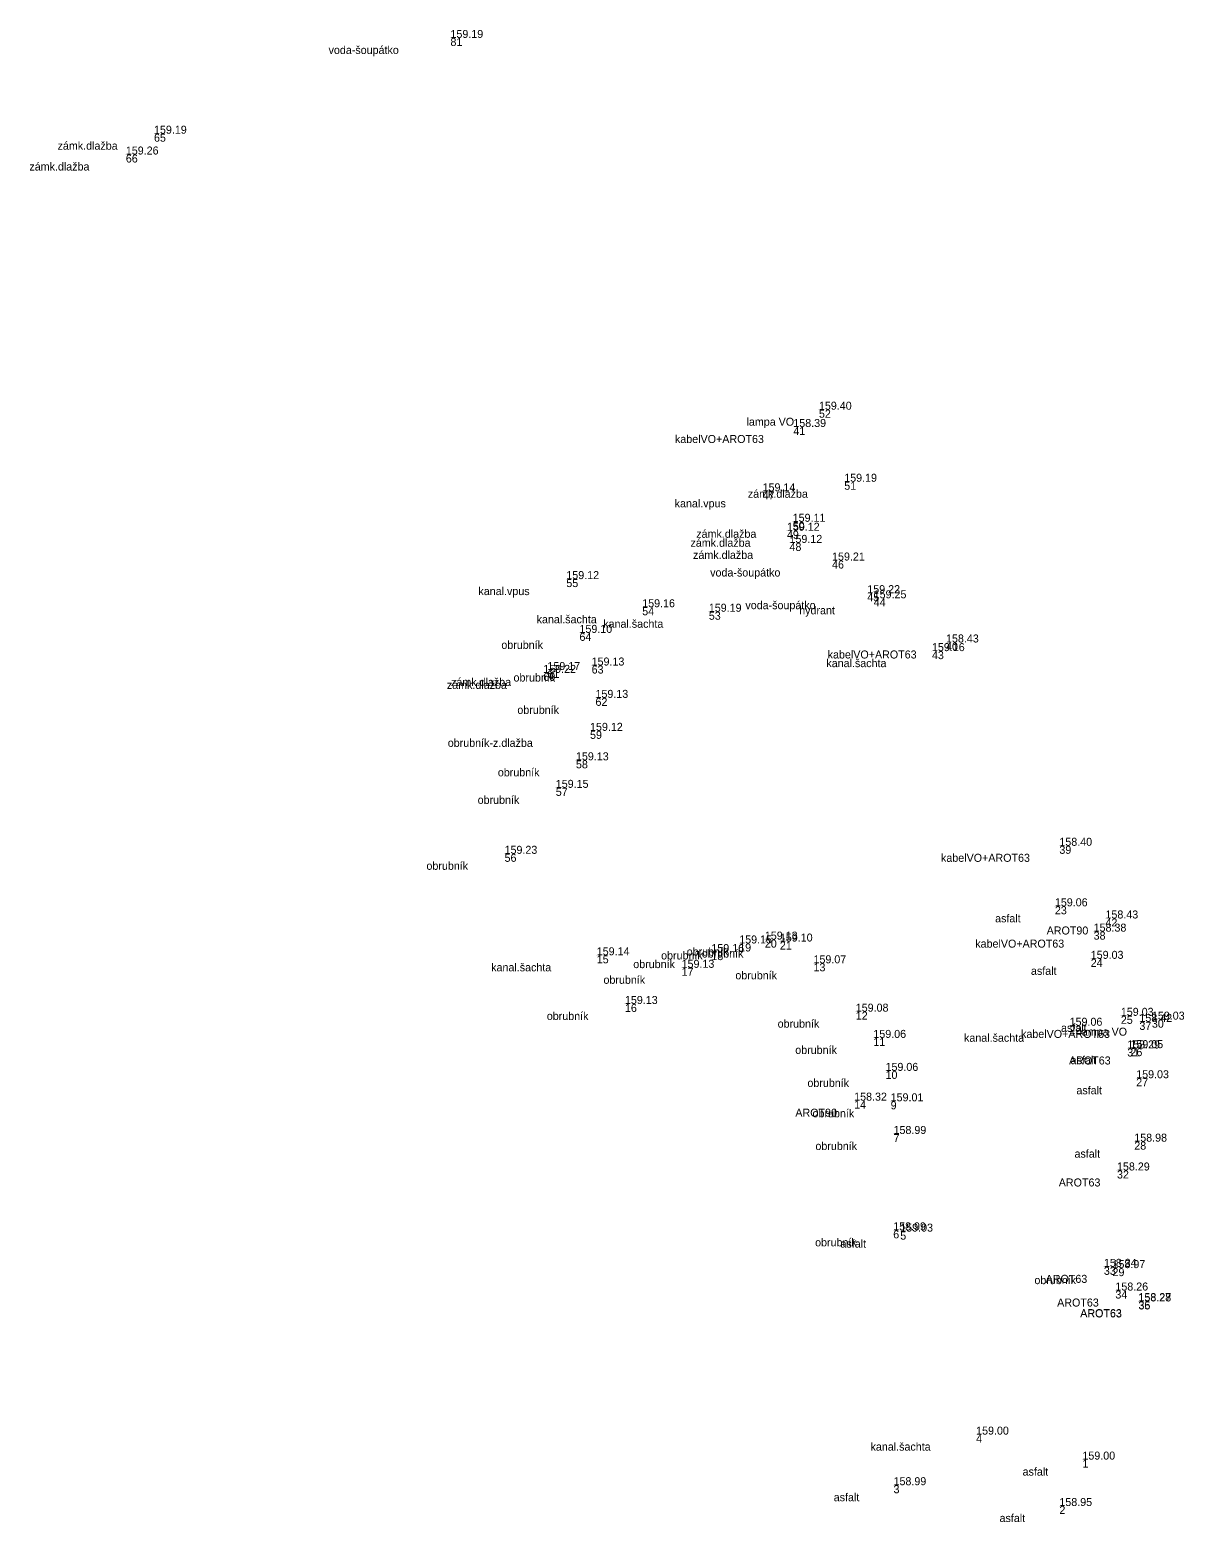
# Model space of a CAD drawing. Extents: x -583304 to -583163, y -1211038 to -1210841.
# Drawn here: x -583199 to -583162.94, y -1211037.82 to -1210991.22 of the extents above; entities that cross this region are included whole.
import ezdxf

# ---------------------------------------------------------------- set-up
doc = ezdxf.new("R2010")
doc.units = 0
for name, color, linetype in [('Vrstva 10', 7, 'Continuous'), ('Vrstva 7', 7, 'Continuous'), ('Vrstva 8', 7, 'Continuous'), ('Vrstva 9', 7, 'Continuous')]:
    doc.layers.add(name, color=color, linetype=linetype)

msp = doc.modelspace()

# ---------------------------------------------------------------- linework, layer by layer
at = {"layer": 'Vrstva 7'}
for p, q in [((-583185.86, -1210991.47), (-583185.86, -1210991.47)), ((-583195.12, -1210994.46), (-583195.12, -1210994.46)), ((-583196, -1210995.11), (-583196, -1210995.11)), ((-583174.35, -1211003.08), (-583174.35, -1211003.08)), ((-583175.15, -1211003.62), (-583175.15, -1211003.62)), ((-583176.11, -1211005.63), (-583176.11, -1211005.63)), ((-583173.56, -1211005.33), (-583173.56, -1211005.33)), ((-583175.17, -1211006.58), (-583175.17, -1211006.58)), ((-583175.35, -1211006.86), (-583175.35, -1211006.86)), ((-583175.27, -1211007.24), (-583175.27, -1211007.24)), ((-583173.94, -1211007.79), (-583173.94, -1211007.79)), ((-583182.24, -1211008.37), (-583182.24, -1211008.37)), ((-583172.84, -1211008.81), (-583172.84, -1211008.81)), ((-583179.87, -1211009.25), (-583179.87, -1211009.25)), ((-583177.79, -1211009.39), (-583177.79, -1211009.39)), ((-583172.64, -1211008.97), (-583172.64, -1211008.97)), ((-583181.83, -1211010.05), (-583181.83, -1211010.05)), ((-583170.82, -1211010.62), (-583170.82, -1211010.62)), ((-583170.38, -1211010.35), (-583170.38, -1211010.35)), ((-583182.83, -1211011.21), (-583182.83, -1211011.21)), ((-583181.45, -1211011.07), (-583181.45, -1211011.07)), ((-583182.96, -1211011.3), (-583182.96, -1211011.3)), ((-583181.33, -1211012.08), (-583181.33, -1211012.08)), ((-583181.5, -1211013.11), (-583181.5, -1211013.11)), ((-583181.94, -1211014.03), (-583181.94, -1211014.03)), ((-583182.57, -1211014.89), (-583182.57, -1211014.89)), ((-583166.84, -1211016.7), (-583166.84, -1211016.7)), ((-583184.17, -1211016.95), (-583184.17, -1211016.95)), ((-583166.98, -1211018.59), (-583166.98, -1211018.59)), ((-583165.4, -1211018.97), (-583165.4, -1211018.97)), ((-583176.04, -1211019.63), (-583176.04, -1211019.63)), ((-583165.77, -1211019.38), (-583165.77, -1211019.38)), ((-583181.29, -1211020.12), (-583181.29, -1211020.12)), ((-583177.71, -1211020.02), (-583177.71, -1211020.02)), ((-583176.84, -1211019.75), (-583176.84, -1211019.75)), ((-583175.57, -1211019.69), (-583175.57, -1211019.69)), ((-583178.64, -1211020.51), (-583178.64, -1211020.51)), ((-583174.52, -1211020.37), (-583174.52, -1211020.37)), ((-583165.86, -1211020.23), (-583165.86, -1211020.23)), ((-583180.41, -1211021.64), (-583180.41, -1211021.64)), ((-583173.2, -1211021.88), (-583173.2, -1211021.88)), ((-583166.52, -1211022.32), (-583166.52, -1211022.32)), ((-583164.92, -1211022.01), (-583164.92, -1211022.01)), ((-583164.34, -1211022.2), (-583164.34, -1211022.2)), ((-583163.95, -1211022.13), (-583163.95, -1211022.13)), ((-583172.65, -1211022.7), (-583172.65, -1211022.7)), ((-583164.72, -1211023.03), (-583164.72, -1211023.03)), ((-583164.62, -1211023.02), (-583164.62, -1211023.02)), ((-583172.27, -1211023.73), (-583172.27, -1211023.73)), ((-583164.44, -1211023.96), (-583164.44, -1211023.96)), ((-583173.25, -1211024.66), (-583173.25, -1211024.66)), ((-583172.11, -1211024.68), (-583172.11, -1211024.68)), ((-583172.02, -1211025.7), (-583172.02, -1211025.7)), ((-583164.5, -1211025.94), (-583164.5, -1211025.94)), ((-583165.04, -1211026.84), (-583165.04, -1211026.84)), ((-583172.03, -1211028.71), (-583172.03, -1211028.71)), ((-583171.81, -1211028.75), (-583171.81, -1211028.75)), ((-583165.45, -1211029.85), (-583165.45, -1211029.85)), ((-583165.18, -1211029.89), (-583165.18, -1211029.89)), ((-583165.09, -1211030.59), (-583165.09, -1211030.59)), ((-583164.37, -1211030.92), (-583164.37, -1211030.92)), ((-583164.37, -1211030.93), (-583164.37, -1211030.93)), ((-583169.44, -1211035.09), (-583169.44, -1211035.09)), ((-583166.12, -1211035.87), (-583166.12, -1211035.87)), ((-583172.02, -1211036.67), (-583172.02, -1211036.67)), ((-583166.84, -1211037.32), (-583166.84, -1211037.32))]:
    msp.add_line(p, q, dxfattribs=at)

# ---------------------------------------------------------------- texts
at = {"layer": 'Vrstva 10'}
for s, p in [('voda-šoupátko', (-583189.667, -1210991.97)), ('zámk.dlažba', (-583198.132, -1210994.96)), ('zámk.dlažba', (-583199.012, -1210995.61)), ('lampa VO', (-583176.612, -1211003.58)), ('kabelVO+AROT63', (-583178.847, -1211004.12)), ('zámk.dlažba', (-583176.572, -1211005.83)), ('kanal.vpus', (-583178.856, -1211006.13)), ('zámk.dlažba', (-583178.182, -1211007.08)), ('zámk.dlažba', (-583178.362, -1211007.36)), ('zámk.dlažba', (-583178.282, -1211007.74)), ('voda-šoupátko', (-583177.747, -1211008.29)), ('kanal.vpus', (-583184.986, -1211008.87)), ('voda-šoupátko', (-583176.647, -1211009.31)), ('hydrant', (-583174.966, -1211009.47)), ('kanal.šachta', (-583183.168, -1211009.75)), ('kanal.šachta', (-583181.088, -1211009.89)), ('obrubník', (-583184.27, -1211010.55)), ('kabelVO+AROT63', (-583174.077, -1211010.85)), ('kanal.šachta', (-583174.118, -1211011.12)), ('zámk.dlažba', (-583185.972, -1211011.8)), ('zámk.dlažba', (-583185.842, -1211011.71)), ('obrubník', (-583183.89, -1211011.57)), ('obrubník', (-583183.77, -1211012.58)), ('obrubník-z.dlažba', (-583185.944, -1211013.61)), ('obrubník', (-583184.38, -1211014.53)), ('obrubník', (-583185.01, -1211015.39)), ('obrubník', (-583186.61, -1211017.45)), ('kabelVO+AROT63', (-583170.537, -1211017.2)), ('asfalt', (-583168.848, -1211019.09)), ('kabelVO+AROT63', (-583169.467, -1211019.88)), ('AROT90', (-583167.237, -1211019.47)), ('obrubník', (-583179.28, -1211020.25)), ('obrubník', (-583178.48, -1211020.13)), ('obrubník', (-583178.01, -1211020.19)), ('kanal.šachta', (-583184.588, -1211020.62)), ('obrubník', (-583180.15, -1211020.52)), ('asfalt', (-583167.728, -1211020.73)), ('obrubník', (-583181.08, -1211021.01)), ('obrubník', (-583176.96, -1211020.87)), ('obrubník', (-583182.85, -1211022.14)), ('obrubník', (-583175.64, -1211022.38)), ('kabelVO+AROT63', (-583168.037, -1211022.7)), ('asfalt', (-583166.788, -1211022.51)), ('lampa VO', (-583166.212, -1211022.63)), ('kanal.šachta', (-583169.818, -1211022.82)), ('obrubník', (-583175.09, -1211023.2)), ('AROT63', (-583166.539, -1211023.53)), ('asfalt', (-583166.488, -1211023.52)), ('obrubník', (-583174.71, -1211024.23)), ('asfalt', (-583166.308, -1211024.46)), ('AROT90', (-583175.087, -1211025.16)), ('obrubník', (-583174.55, -1211025.18)), ('obrubník', (-583174.46, -1211026.2)), ('asfalt', (-583166.368, -1211026.44)), ('AROT63', (-583166.859, -1211027.34)), ('obrubník', (-583174.47, -1211029.21)), ('asfalt', (-583173.678, -1211029.25)), ('obrubník', (-583167.62, -1211030.39)), ('AROT63', (-583167.269, -1211030.35)), ('AROT63', (-583166.909, -1211031.09)), ('AROT63', (-583166.189, -1211031.42)), ('AROT63', (-583166.189, -1211031.43)), ('kanal.šachta', (-583172.738, -1211035.59)), ('asfalt', (-583167.988, -1211036.37)), ('asfalt', (-583173.888, -1211037.17)), ('asfalt', (-583168.708, -1211037.82))]:
    msp.add_text(s, height=0.25, dxfattribs=at).set_placement(p)
at = {"layer": 'Vrstva 8'}
for s, p in [('81', (-583185.86, -1210991.72)), ('65', (-583195.12, -1210994.71)), ('66', (-583196, -1210995.36)), ('52', (-583174.35, -1211003.33)), ('41', (-583175.15, -1211003.87)), ('47', (-583176.11, -1211005.88)), ('51', (-583173.56, -1211005.58)), ('50', (-583175.17, -1211006.83)), ('49', (-583175.35, -1211007.11)), ('48', (-583175.27, -1211007.49)), ('46', (-583173.94, -1211008.04)), ('55', (-583182.24, -1211008.62)), ('45', (-583172.84, -1211009.06)), ('54', (-583179.87, -1211009.5)), ('53', (-583177.79, -1211009.64)), ('44', (-583172.64, -1211009.22)), ('64', (-583181.83, -1211010.3)), ('43', (-583170.82, -1211010.87)), ('40', (-583170.38, -1211010.6)), ('61', (-583182.83, -1211011.46)), ('63', (-583181.45, -1211011.32)), ('60', (-583182.96, -1211011.55)), ('62', (-583181.33, -1211012.33)), ('59', (-583181.5, -1211013.36)), ('58', (-583181.94, -1211014.28)), ('57', (-583182.57, -1211015.14)), ('39', (-583166.84, -1211016.95)), ('56', (-583184.17, -1211017.2)), ('23', (-583166.98, -1211018.84)), ('42', (-583165.4, -1211019.22)), ('20', (-583176.04, -1211019.88)), ('38', (-583165.77, -1211019.63)), ('15', (-583181.29, -1211020.37)), ('18', (-583177.71, -1211020.27)), ('19', (-583176.84, -1211020)), ('21', (-583175.57, -1211019.94)), ('17', (-583178.64, -1211020.76)), ('13', (-583174.52, -1211020.62)), ('24', (-583165.86, -1211020.48)), ('16', (-583180.41, -1211021.89)), ('12', (-583173.2, -1211022.13)), ('22', (-583166.52, -1211022.57)), ('25', (-583164.92, -1211022.26)), ('37', (-583164.34, -1211022.45)), ('30', (-583163.95, -1211022.38)), ('11', (-583172.65, -1211022.95)), ('31', (-583164.72, -1211023.28)), ('26', (-583164.62, -1211023.27)), ('10', (-583172.27, -1211023.98)), ('27', (-583164.44, -1211024.21)), ('14', (-583173.25, -1211024.91)), ('9', (-583172.11, -1211024.93)), ('7', (-583172.02, -1211025.95)), ('28', (-583164.5, -1211026.19)), ('32', (-583165.04, -1211027.09)), ('6', (-583172.03, -1211028.96)), ('5', (-583171.81, -1211029)), ('33', (-583165.45, -1211030.1)), ('29', (-583165.18, -1211030.14)), ('34', (-583165.09, -1211030.84)), ('36', (-583164.37, -1211031.17)), ('35', (-583164.37, -1211031.18)), ('4', (-583169.44, -1211035.34)), ('1', (-583166.12, -1211036.12)), ('3', (-583172.02, -1211036.92)), ('2', (-583166.84, -1211037.57))]:
    msp.add_text(s, height=0.25, dxfattribs=at).set_placement(p)
at = {"layer": 'Vrstva 9'}
for s, p in [('159.19 ', (-583185.86, -1210991.47)), ('159.19 ', (-583195.12, -1210994.46)), ('159.26 ', (-583196, -1210995.11)), ('159.40 ', (-583174.35, -1211003.08)), ('158.39 ', (-583175.15, -1211003.62)), ('159.19 ', (-583173.56, -1211005.33)), ('159.14 ', (-583176.11, -1211005.63)), ('159.11 ', (-583175.17, -1211006.58)), ('159.12 ', (-583175.35, -1211006.86)), ('159.12 ', (-583175.27, -1211007.24)), ('159.21 ', (-583173.94, -1211007.79)), ('159.12 ', (-583182.24, -1211008.37)), ('159.22 ', (-583172.84, -1211008.81)), ('159.25 ', (-583172.64, -1211008.97)), ('159.16 ', (-583179.87, -1211009.25)), ('159.19 ', (-583177.79, -1211009.39)), ('159.10 ', (-583181.83, -1211010.05)), ('158.43 ', (-583170.38, -1211010.35)), ('159.16 ', (-583170.82, -1211010.62)), ('159.22 ', (-583182.96, -1211011.3)), ('159.17 ', (-583182.83, -1211011.21)), ('159.13 ', (-583181.45, -1211011.07)), ('159.13 ', (-583181.33, -1211012.08)), ('159.12 ', (-583181.5, -1211013.11)), ('159.13 ', (-583181.94, -1211014.03)), ('159.15 ', (-583182.57, -1211014.89)), ('159.23 ', (-583184.17, -1211016.95)), ('158.40 ', (-583166.84, -1211016.7)), ('159.06 ', (-583166.98, -1211018.59)), ('158.43 ', (-583165.4, -1211018.97)), ('158.38 ', (-583165.77, -1211019.38)), ('159.15 ', (-583176.84, -1211019.75)), ('159.13 ', (-583176.04, -1211019.63)), ('159.10 ', (-583175.57, -1211019.69)), ('159.14 ', (-583181.29, -1211020.12)), ('159.16 ', (-583177.71, -1211020.02)), ('159.07 ', (-583174.52, -1211020.37)), ('159.03 ', (-583165.86, -1211020.23)), ('159.13 ', (-583178.64, -1211020.51)), ('159.13 ', (-583180.41, -1211021.64)), ('159.08 ', (-583173.2, -1211021.88)), ('159.03 ', (-583164.92, -1211022.01)), ('158.42 ', (-583164.34, -1211022.2)), ('159.03 ', (-583163.95, -1211022.13)), ('159.06 ', (-583172.65, -1211022.7)), ('159.06 ', (-583166.52, -1211022.32)), ('158.29 ', (-583164.72, -1211023.03)), ('159.05 ', (-583164.62, -1211023.02)), ('159.06 ', (-583172.27, -1211023.73)), ('159.03 ', (-583164.44, -1211023.96)), ('158.32 ', (-583173.25, -1211024.66)), ('159.01 ', (-583172.11, -1211024.68)), ('158.99 ', (-583172.02, -1211025.7)), ('158.98 ', (-583164.5, -1211025.94)), ('158.29 ', (-583165.04, -1211026.84)), ('158.99 ', (-583172.03, -1211028.71)), ('159.03 ', (-583171.81, -1211028.75)), ('158.34 ', (-583165.45, -1211029.85)), ('158.97 ', (-583165.18, -1211029.89)), ('158.26 ', (-583165.09, -1211030.59)), ('158.27 ', (-583164.37, -1211030.92)), ('158.28 ', (-583164.37, -1211030.93)), ('159.00 ', (-583169.44, -1211035.09)), ('159.00 ', (-583166.12, -1211035.87)), ('158.99 ', (-583172.02, -1211036.67)), ('158.95 ', (-583166.84, -1211037.32))]:
    msp.add_text(s, height=0.25, dxfattribs=at).set_placement(p)

doc.saveas('drawing.dxf')
